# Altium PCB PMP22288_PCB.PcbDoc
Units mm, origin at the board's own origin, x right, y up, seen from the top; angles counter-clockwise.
Board outline 85.25 x 60.01 mm, 2 copper layers (Top Layer, Bottom Layer), stack 1.575 mm thick; 43 components, 22 nets, 97 pads, 29 vias.
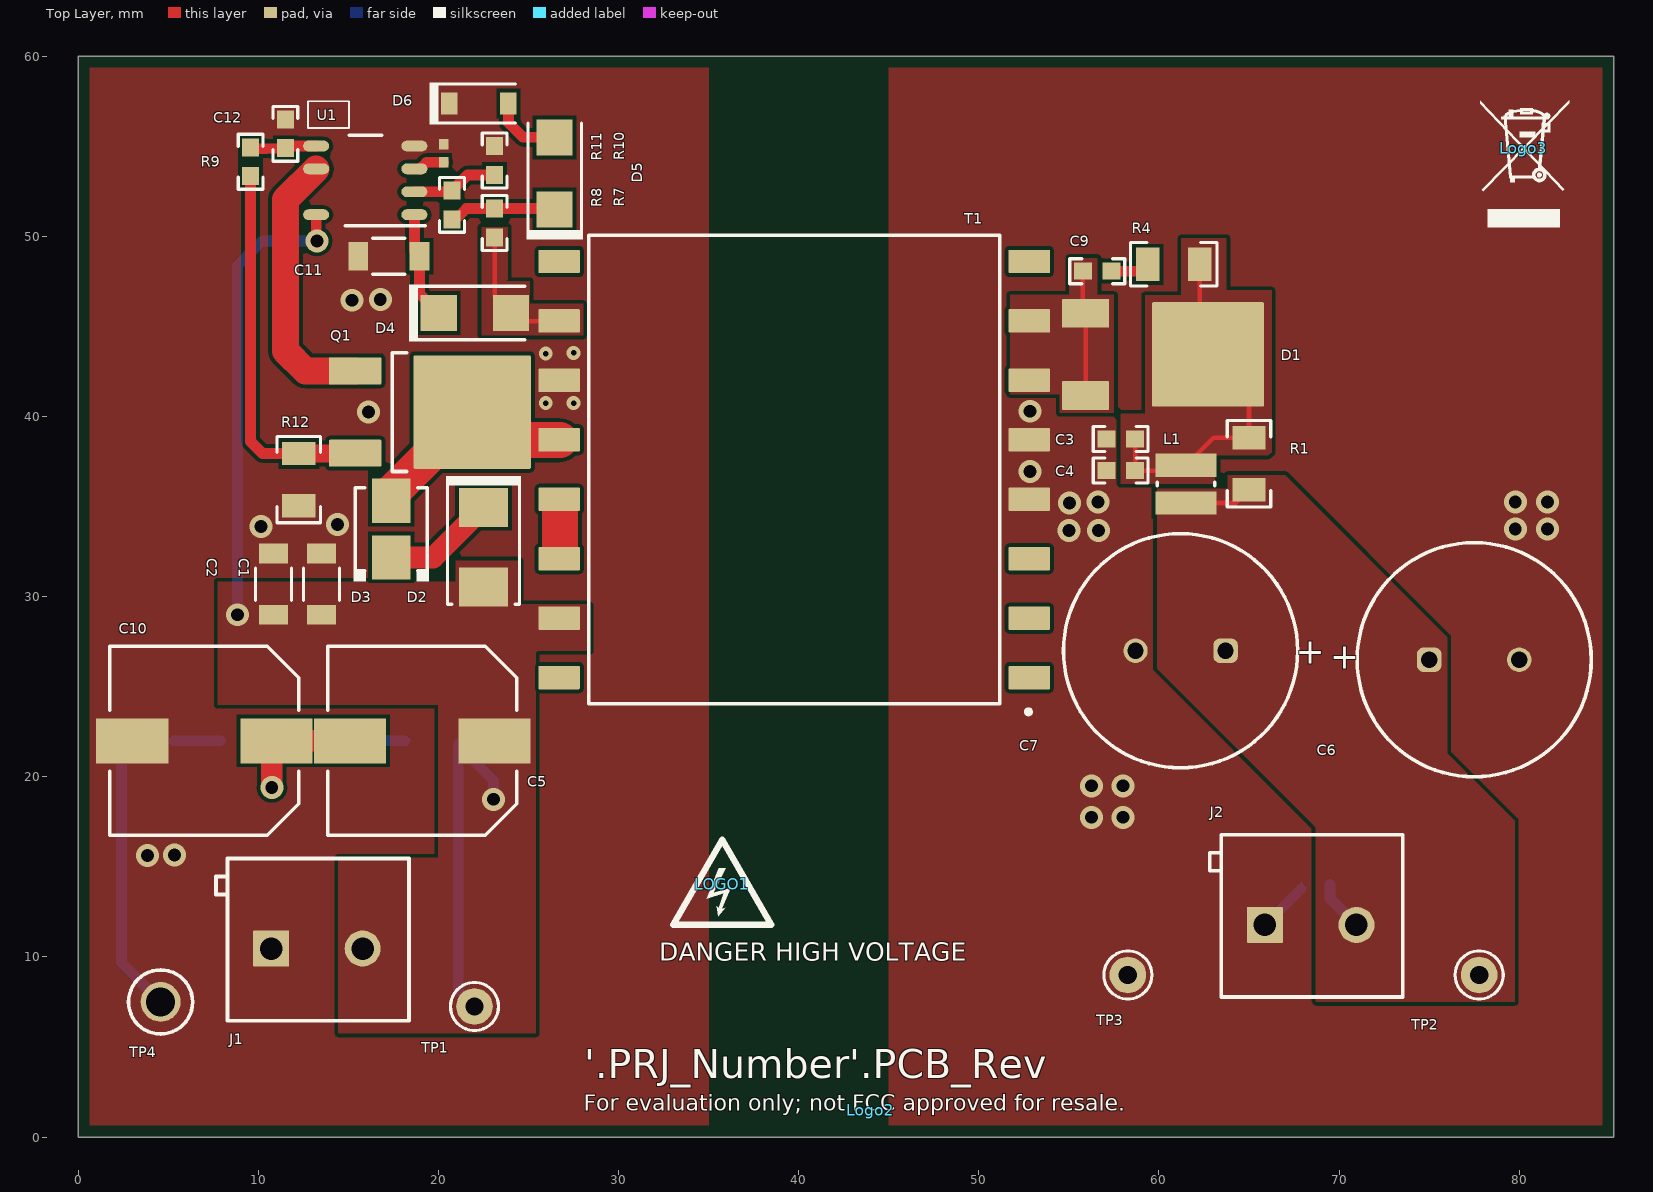
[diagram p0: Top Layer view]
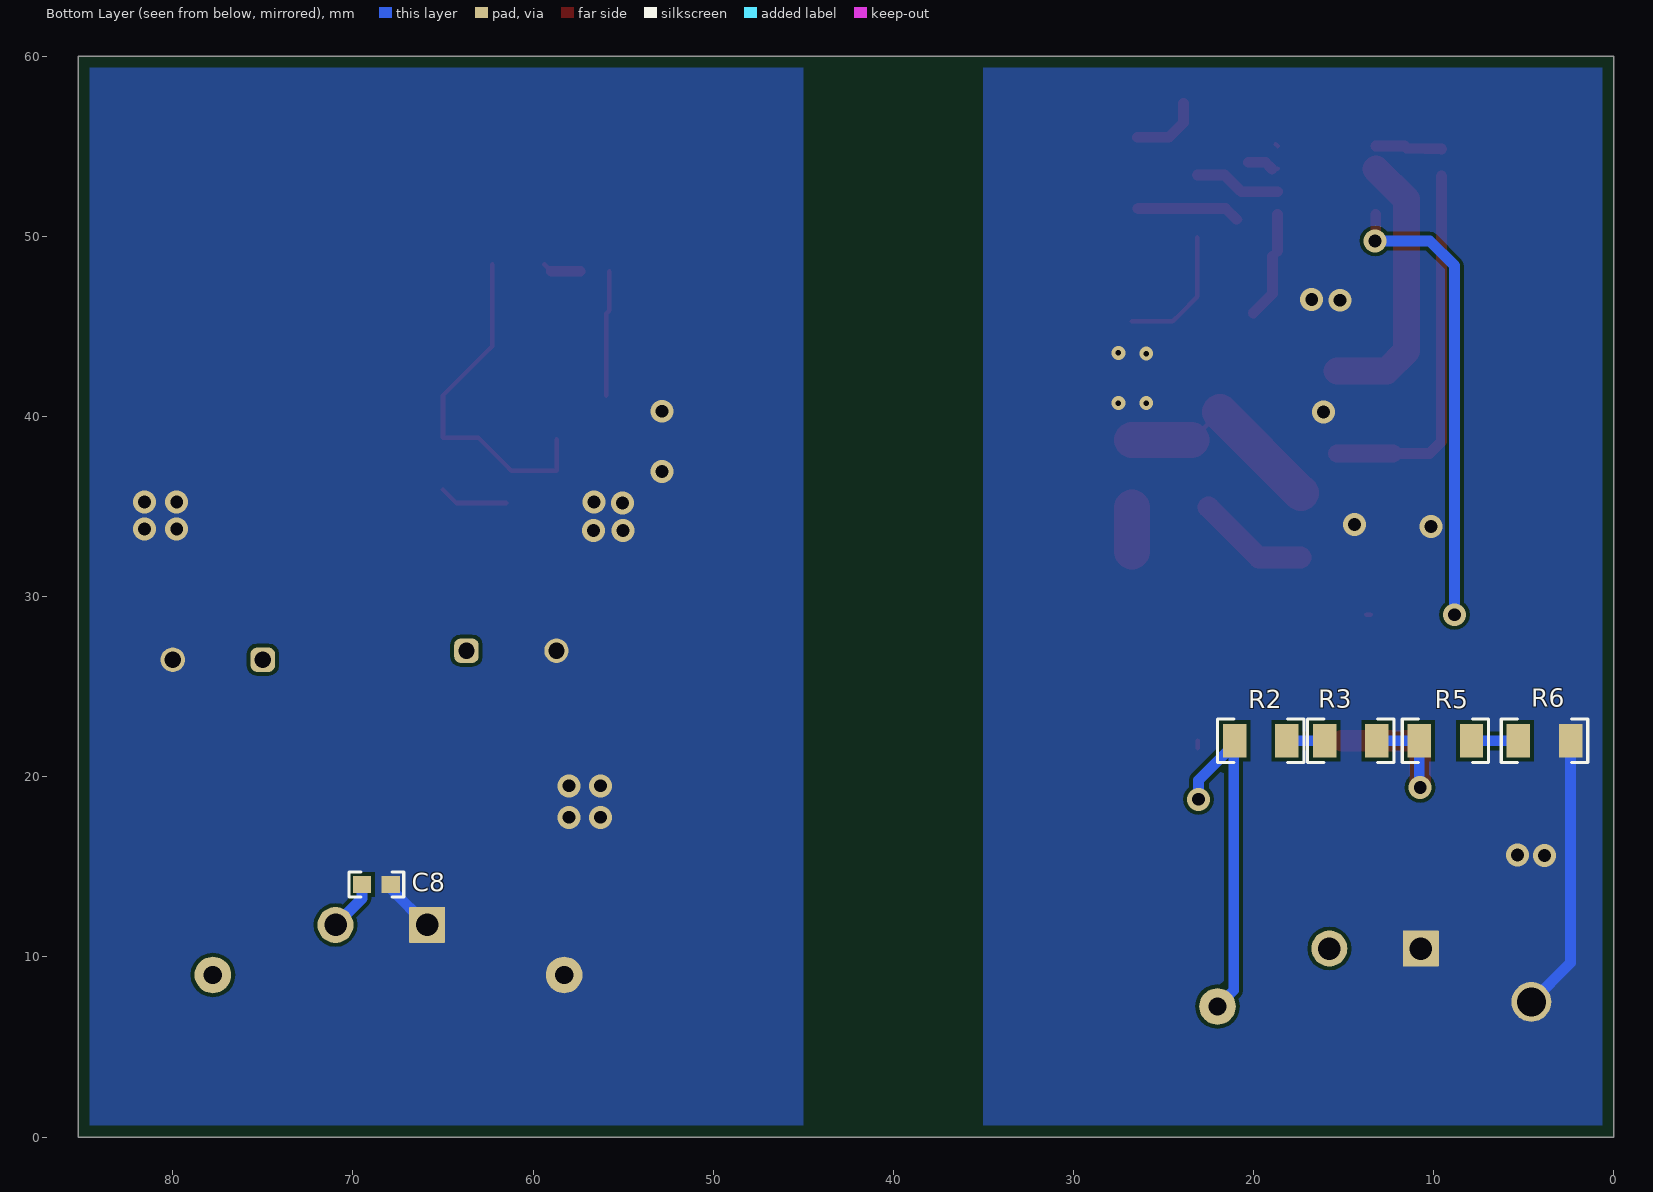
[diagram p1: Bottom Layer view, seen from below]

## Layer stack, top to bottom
Top Solder: solder mask 0.0102, Solder Resist, Dk 3.5
Top Layer: signal copper 0.0356
Dielectric1: core 1.5037, FR-4, Dk 4.8
Bottom Layer: signal copper 0.0356
Bottom Solder: solder mask 0.0102, Solder Resist, Dk 3.5

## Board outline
0,0 85.25,0 85.25,60.005 0,60.005

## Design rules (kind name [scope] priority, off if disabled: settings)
AcuteAngle [All] p1: minimum=4.50000000000000E+0001 checktracksonly=FALSE
AssemblyTestPointUsage [All] p1: valid=2
BoardOutlineClearance BoardOutlineClearance_MountingHoles [OnCopper and InComponentClass('Mounting Holes')] p1: gap=0.635 ignorepadtopadclearanceinfootprint=FALSE
BoardOutlineClearance BoardOutlineClearance_Poly [OnCopper and InPoly] p2: gap=0.635 ignorepadtopadclearanceinfootprint=FALSE
BoardOutlineClearance [OnCopper and Not InComponentClass('Logo') and not InComponentClass('FiducialMark') and not InRegion(1000,500,4000,800)] p3: gap=0.635 ignorepadtopadclearanceinfootprint=FALSE
Clearance Clearance_Keepouts [((IsTrack Or IsArc) And Not InPoly) And IsFree and IsKeepOut vs ((IsTrack Or IsArc) And Not InPoly) And IsFree and IsKeepOut] p1: gap=0 ignorepadtopadclearanceinfootprint=FALSE
Clearance Clearance_Poly [InPolygon] p2: gap=0.203 ignorepadtopadclearanceinfootprint=FALSE except(0: Arc-Hole Track-Hole SMDPad-Hole THPad-Hole Via-Hole Fill-Hole Poly-Hole Region-Hole Text-Hole)
Clearance [All] p3: gap=0.2 ignorepadtopadclearanceinfootprint=FALSE except(0: Arc-Hole Track-Hole SMDPad-Hole THPad-Hole Via-Hole Fill-Hole Poly-Hole Region-Hole Text-Hole)
ComponentClearance ComponentClearance_MountingHoles_FiducialMarks [InComponentClass('Mounting Holes') vs InComponentClass('FiducialMark')] p1: gap=1.27 collisioncheckmode=3 verticalgap=0.254 showdistances=FALSE
ComponentClearance ComponentClearance_Shunt [InComponentClass('Header') vs InComponentClass('Shunt')] p2: gap=0 collisioncheckmode=3 verticalgap=0 showdistances=FALSE
ComponentClearance ComponentClearance_Logo [InComponentClass('Logo')] p3: gap=1.27 collisioncheckmode=3 verticalgap=0.254 showdistances=FALSE
ComponentClearance ComponentClearance_ScrewToNut [(HasFootprint('NY PMS 440 0025 PH')) vs (HasFootprint('Keystone_1902C'))] p4: gap=0.127 collisioncheckmode=3 verticalgap=0.254 showdistances=FALSE
ComponentClearance ComponentClearance_MountingHoles [InComponentClass('Mounting Holes')] p5: gap=6.35 collisioncheckmode=3 verticalgap=2540 showdistances=FALSE
ComponentClearance ComponentClearance_SmallPassives [HasFootprint('0201*') or HasFootprint('0402*') or HasFootprint('0508') or HasFootprint('0603*') or HasFootprint('0612') or HasFootprint('0805*') or HasFootprint('0815*') or HasFootprint('0830*') or HasFootprint('1206*') or HasFootprint('1210*') or HasFootprint('1808*') or HasFootprint('1812*') or HasFootprint('1825*') or HasFootprint('2010*') or HasFootprint('2220*') or HasFootprint('2225*') or HasFootprint('2512*') or HasFootprint('2728*') or HasFootprint('3518*') vs HasFootprint('0201*') or HasFootprint('0402*') or HasFootprint('0508') or HasFootprint('0603*') or HasFootprint('0612') or HasFootprint('0805*') or HasFootprint('0815*') or HasFootprint('0830*') or HasFootprint('1206*') or HasFootprint('1210*') or HasFootprint('1808*') or HasFootprint('1812*') or HasFootprint('1825*') or HasFootprint('2010*') or HasFootprint('2220*') or HasFootprint('2225*') or HasFootprint('2512*') or HasFootprint('2728*') or HasFootprint('3518*')] p6: gap=0.38 collisioncheckmode=3 verticalgap=0.254 showdistances=FALSE
ComponentClearance ComponentClearance_THtoSMT [IsThruComponent vs IsSMTComponent] p7: gap=0.381 collisioncheckmode=3 verticalgap=0.762 showdistances=FALSE
ComponentClearance ComponentClearance_THtoTH [IsThruComponent vs IsThruComponent] p8: gap=0.381 collisioncheckmode=3 verticalgap=0.762 showdistances=FALSE
ComponentClearance [All] p9: gap=0.381 collisioncheckmode=3 verticalgap=0.254 showdistances=FALSE
DiffPairsRouting [All] p1: maxlimit=2.54 minlimit=0.254 mostfreqgap=0.254 toplayer_minwidth=0.381 toplayer_maxwidth=0.381 toplayer_prefwidth=0.381 bottomlayer_minwidth=0.381 bottomlayer_maxwidth=0.381 bottomlayer_prefwidth=0.381 maxuncoupledlength=25.4
FabricationTestPointUsage TestPointUsage [All] p1: valid=2 allowmultiple=FALSE
FabricationTestpoint Testpoint [All] p1: side=3 testpointundercomponent=TRUE minsize=1.016 maxsize=2.54 preferedsize=1.524 minholesize=0 maxholesize=1.016 preferedholesize=0.813 testpointgrid=0.025 allowsidetop=TRUE allowsidebottom=TRUE usegrid=TRUE gridtolerance=0
FanoutControl Fanout_LCC [IsLCC] p1: bgadir=Out bgaviamode=Centered fanoutstyle=Auto fanoutdirection=Alternating viagrid=0.025 // Fanout_LCC (Default Rule)
FanoutControl Fanout_BGA [IsBGA] p2: bgadir=Out bgaviamode=Centered fanoutstyle=Auto fanoutdirection=Alternating viagrid=0.025 // Fanout_BGA (Default Rule)
FanoutControl Fanout_Default [All] p4: bgadir=Out bgaviamode=Centered fanoutstyle=Auto fanoutdirection=Alternating viagrid=0.025 // Fanout_Default (Default Rule)
FanoutControl Fanout_Small [(CompPinCount < 5)] p5: bgadir=Out bgaviamode=Centered fanoutstyle=Auto fanoutdirection=OutThenIn viagrid=0.025 // Fanout_Small (Default Rule)
HoleSize [All] p1: absolutevalues=TRUE maxlimit=6.375 minlimit=0.2 maxpercent=80.000 minpercent=20.000
MinimumAnnularRing MinimumAnnularRing_ThermalPadVias [IsVia and InAnyComponent] p1: minimumring=0.15
MinimumAnnularRing [All] p2: minimumring=0.203
MinimumSolderMaskSliver MinimumSolderMaskSliver_Logo [InComponentClass('Logo') vs InComponentClass('Logo')] p1: minsoldermaskwidth=0.018
MinimumSolderMaskSliver [All] p2: minsoldermaskwidth=0.1
PlaneConnect [All] p1: planeconnectstyle=Direct reliefexpansion=0.254 reliefentries=4 reliefconductorwidth=0.254 reliefairgap=0.254
PolygonConnect [All] p1: connectstyle=Direct reliefconductorwidth=0.254 reliefentries=4 polygonreliefangle="90 Angle" airgapwidth=0.254
RoutingVias ThermalPadVias [IsVia and InAnyComponent] p1: holewidth=0.2 width=0.5 viastyle="Through Hole" minholewidth=0.2 minwidth=0.5 maxholewidth=0.33 maxwidth=0.6
RoutingVias [All] p2: holewidth=0.406 width=0.864 viastyle="Through Hole" minholewidth=0.2 minwidth=0.66 maxholewidth=1.016 maxwidth=1.651
SilkToBoardRegionClearance [Not ((IsComment or IsDesignator) And (Hide <> 'False')) and not InRegion(1000,500,4000,800)] p1:
SilkToSilkClearance SilkToSilkClearance_Pb-FreeLogo [(HasFootprint('Pb-Free_Overlay_Medium') OR HasFootprint('Pb-Free_Overlay_Small')) vs (HasFootprint('Pb-Free_Overlay_Medium') OR HasFootprint('Pb-Free_Overlay_Small'))] p1: silktosilkclearance=0
SilkToSilkClearance [All] p2: silktosilkclearance=0.102
SilkToSolderMaskClearance SilkToComponentPadClearance [IsPad and InAnycomponent] p1: minsilkscreentomaskgap=0.127 clearancetoexposedcopper=TRUE
SilkToSolderMaskClearance "Silk to Solder Mask Opening" [All] p2: minsilkscreentomaskgap=0.102 clearancetoexposedcopper=FALSE
SolderMaskExpansion [All] p1: expansion=0.05
Width [All] p1: maxlimit=2.54 minlimit=0.152 preferedwidth=0.254 checkconnectedcopper=TRUE
15 further rules are at their usual default settings.

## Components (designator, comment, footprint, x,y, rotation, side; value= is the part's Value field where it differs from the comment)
C1 "C1206C223KDRACTU" 1206_190 13.5,30.7 r90 top value=0.022uF
C2 "C1206C223KDRACTU" 1206_190 10.85,30.7 r90 top value=0.022uF
C3 "GRM188R71E105KA12D" 0603 57.873,38.75 r180 top value=1uF
C4 "GRM188R71E105KA12D" 0603 57.873,37 r180 top value=1uF
C5 "ULV2G100MNL1GS" ULV_1000x1350 19.1,22 r180 top value=10uF
C6 "EEU-FC1V391S" FC_1250x1500 77.5,26.5 r0 top value=390uF
C7 "EEU-FC1V391S" FC_1250x1500 61.198,27 r180 top value=390uF
C8 "C0603C104K5RACAUTO" 0603 68.698,14.025 r180 bottom value=0.1uF
C9 "CGA3E2X7R2A103K080AA" 0603 56.575,48.069 r180 top value=0.01uF
C10 "ULV2G100MNL1GS" ULV_1000x1350 7,22 r180 top value=10uF
C11 "CGA5L1X7R1V106K160AC" 1206_190 17.25,48.899 r180 top value=10uF
C12 "CGA3E2NP01H101J080AA" 0603 11.5,55.695 r90 top value=100pF
D1 "MBRD20200CT-13" DPAK 59.323,43.45 r0 top value=200V
D2 "1SMB5956BT3G" SMB 22.5,32.75 r270 top value=200V
D3 "EGF1T-E3/67A" DO-214BA 17.375,33.75 r90 top value=1300V
D4 "US1J-E3/5AT" SMA 22.017,45.75 r0 top value=600V
D5 "US1J-E3/5AT" SMA 26.451,53.499 r90 top value=600V
D6 "DDZ20CQ-7" SOD-123 22.25,57.382 r0 top value=20V
J1 "ED120/2DS" On-Shore_ED120_2DS 13.25,10.466 r0 top
J2 "ED120/2DS" On-Shore_ED120_2DS 68.423,11.775 r0 top
L1 "784383350047" WE-MAIA_3015 61.498,36.25 r270 top value=470nH
LOGO1 "DANGER HIGH VOLTAGE" IEC_HighVoltage_Small 35.75,14.025 r0 top
Logo2 "FCC disclaimer" FCC_disclaimer 44,1.5 r0 top
Logo3 "WEEE logo" WEEE_Minimum 80.25,54.895 r0 top
Q1 "STD3N95K5AG" FP-STD3N95K5AG_DPAK-MFG 19.525,40.249 r270 top
R1 "CRCW12060000Z0EA" 1206 64.998,37.381 r270 top value=0
R2 "CRCW12061M00FKEA" 1206 19.6,22 r180 bottom value=1.00Meg
R3 "CRCW12061M00FKEA" 1206 14.6,22 r180 bottom value=1.00Meg
R4 "CRCW12060000Z0EA" 1206 60.823,48.45 r0 top value=0
R5 "CRCW12061M00FKEA" 1206 9.35,22 r180 bottom value=1.00Meg
R6 "CRCW12061M00FKEA" 1206 3.85,22 r180 bottom value=1.00Meg
R7 "CRCW060323K2FKEA" 0603 23.119,50.741 r270 top value=23.2k
R8 "CRCW06031K69FKEA" 0603 20.75,51.75 r270 top value=1.69k
R9 "CRCW06031K02FKEA" 0603 9.572,54.145 r270 top value=1.02k
R10 "CRCW06038K66FKEA" 0603 23.119,54.216 r270 top value=8.66k
R11 "CRCW0402332KFKED" 0402L 20.294,54.616 r270 top value=332k
R12 "CSR1206FT1R00" 1206 12.25,36.5 r90 top value=1.00
T1 "P302264-A1-51" FP-P302264-A1-51_SMD_TRANSFORMER_26MM0_22MM8-MFG 39.75,37.058 r90 top
TP1 "5000" Keystone5000 22,7.25 r90 top
TP2 "5000" Keystone5000 77.773,9 r270 top
TP3 "5001" Keystone5001 58.273,9 r270 top
TP4 "5011" Keystone5011 4.575,7.5 r0 top
U1 "UCC28730QDRQ1" D0007A_N 15.937,53.114 r180 top

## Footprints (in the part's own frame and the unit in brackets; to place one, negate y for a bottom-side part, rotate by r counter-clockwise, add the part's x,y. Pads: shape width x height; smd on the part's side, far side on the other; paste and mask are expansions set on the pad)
0402L [mm] "0402 from SM-752 data"
  rect 0.6x0.5 smd: 1(-0.5,0) 2(0.5,0)
  body extent -0.55,-0.3 0.55,0.3, height 0.6
0603 [mm] "0603 from SM-752 data"
  rect 1x0.95 smd: 1(-0.8,0) 2(0.8,0)
  silkscreen extent -1.52,-0.69 1.52,0.69, body extent -0.87,-0.47 0.87,0.47, height 1
1206 [mm] "1206 from SM-752 data"
  rect 1.3x1.85 smd: 1(-1.45,0) 2(1.45,0)
  silkscreen extent -2.4,-1.21 2.4,1.21, body extent -1.7,-0.9 1.7,0.9, height 1.35
1206_190 [mm] "1206_190"
  rect 1.1x1.6 smd: 1(-1.7,0) 2(1.7,0)
  silkscreen extent -0.9,-1 0.9,1, body extent -1.75,-0.95 1.75,0.95, height 1.9
D0007A_N [mm] "SOIC, 7-Leads, Body 4.9x3.9mm, Pitch 1.27mm, IPC Medium Density"
  oval 1.45x0.6 smd: 1(-2.725,1.905) 2(-2.725,0.635) 3(-2.725,-0.635) 4(-2.725,-1.905) 5(2.725,-1.905) 6(2.725,-0.635) 8(2.725,1.905)
  silkscreen extent -3.32,-2.5 1.1,2.52, body extent -3.01,-2.45 3.01,2.45, height 1.75
DO-214BA [mm] "Molded Diode, 2-Leads, Body 4.3x3.6mm, IPC Medium Density"
  rect 2.45x2.15 smd: 1(-1.575,0) 2(1.575,0)
  silkscreen extent -2.92,-2.1 2.3,2.1, body extent -2.29,-1.97 2.28,1.97, height 3.3
DPAK [mm] "D-PAK, 3-Pads, Body 6.22x6.73mm (max), TO-252AA using nominal STEP model"
  rrect6% 2.6x1.6 smd: 1(-3.4,2.28) 3(-3.4,-2.28)
  rrect2% 6.2x5.8 smd paste-3: 2(3.4,0)
  body extent -3.86,-3.29 5.84,3.29, height 2.48
FC_1250x1500 [mm] "TH, 2-Leads, Dia 12.5mm, Pin Spacing 5mm"
  rrect50% 1.35x1.35 hole 0.9: 1(-2.5,0)
  round 1.35 hole 0.9: 2(2.5,0)
  silkscreen extent -6.5,-6.5 6.5,6.5, body extent -6.5,-6.5 6.51,6.5, height 16.01
FCC_disclaimer [mm]
FP-P302264-A1-51_SMD_TRANSFORMER_26MM0_22MM8-MFG [mm]
  rrect8% 1.3x2.3 smd paste+0 mask+0: 1(-11.55,-13.05) 2(-8.25,-13.05) 3(-4.95,-13.05) 4(-1.65,-13.05) 5(1.65,-13.05) 6(4.95,-13.05) 7(8.25,-13.05) 8(11.55,-13.05) 9(11.55,13.05) 10(8.25,13.05) 11(4.95,13.05) 12(1.65,13.05) 13(-1.65,13.05) 14(-4.95,13.05) 15(-8.25,13.05) 16(-11.55,13.05)
  silkscreen extent -13.57,-13.13 13,11.4, body extent -13.1,-14.3 13.1,14.3, height 0.25
FP-STD3N95K5AG_DPAK-MFG [mm]
  rrect7% 1.5x2.9 smd paste+0 mask+0: 1(-2.286,-4.15) 3(2.286,-4.15)
  rrect2% 6.3x6.5 smd paste+0 mask+0: 4(0,2.35)
  silkscreen extent -3.3,-2.09 3.3,-1.28, body extent -3.4,-5.7 3.4,5.7, height 0.25
IEC_HighVoltage_Small [mm]
  silkscreen extent -2.72,-2.24 2.72,2.47
Keystone5000 [mil] "For Keystone 500x miniature loop terminals"
  round 80 hole 40: 1(0,0)
  silkscreen extent -52,-52 52,52, body extent -49,-49 49,49, height 182
Keystone5001 [mil] "For Keystone 500x miniature loop terminals"
  round 80 hole 40: 1(0,0)
  silkscreen extent -52,-52 52,52, body extent -49,-49 49,49, height 182
Keystone5011 [mil] "Keystone Multipurpose loops"
  round 87 hole 63: 1(0,0)
  silkscreen extent -70,-70 70,70, body extent -63,-63 63,62, height 319
On-Shore_ED120_2DS [mm] "ONSHORE"
  rrect5% 2x2 hole 1.25: 1(-2.54,0)
  round 2 hole 1.25: 2(2.54,0)
  silkscreen extent -5.6,-4 5.12,5, body extent -5.78,-4 5.08,5, height 13
SMA [mm] "Molded Diode, 2-Leads, Body 4.3x2.6mm, IPC Medium Density, based on OnSemi component dimensions and land pattern"
  rect 2x2 smd: 1(-2,0) 2(2,0)
  silkscreen extent -3.66,-1.57 2.79,1.57, body extent -2.6,-1.3 2.6,1.3, height 2.42
SMB [mm] "Molded Diode, 2-Leads, Body 5.4x3.6mm, IPC Medium Density, based on OnSemi component dimensions"
  rect 2.159x2.743 smd: 1(-2.21,0) 2(2.21,0)
  silkscreen extent -3.94,-2.08 3.18,2.08, body extent -2.7,-1.8 2.7,1.8, height 2.32
SOD-123 [mm] "On Semi recommended land pattern"
  rect 0.915x1.22 smd: 1(-1.637,0) 2(1.637,0)
  silkscreen extent -2.74,-1.17 2.03,1.17, body extent -1.93,-0.9 1.93,0.9, height 1.35
ULV_1000x1350 [mm] "SMD, 2-Leads, Dia 10mm"
  rect 4x2.5 smd: 1(-4,0) 2(4,0)
  silkscreen extent -5.25,-5.25 5.25,5.25, body extent -5.25,-5.25 5.25,5.25, height 14.51
WE-MAIA_3015 [mm] "SMD, 2-Leads, Body 3x3mm"
  rect 1.3x3.4 smd: 1(-1.05,0) 2(1.05,0)
  silkscreen extent -0.1,-1.6 0.1,1.6, body extent -1.6,-1.6 1.6,1.6, height 1.5
WEEE_Minimum [mm] "WEEElie bin"
  silkscreen extent -2.42,-4.38 2.52,2.65

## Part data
C1 C2: library part CMP-0084048-1, "CAP, CERM, 0.022 µF, 1000 V,+/- 10%, X7R, AEC-Q200 Grade 1, 1206", Cap_Case=1206, Manufacturer=Kemet, TempCo=X7R, Tolerance_%=10%, Value2=1000V, ValueDisplayed=0.022µF
C3 C4: library part CMP-0007405-4, "CAP, CERM, 1 uF, 25 V, +/- 10%, X7R, 0603", Cap_Case=0603, Manufacturer=MuRata, Supplier Part Number 1=490-5307-1-ND, TempCo=X7R, Tolerance_%=10%, Value1=Unknown, Value2=25V, ValueDisplayed=1uF
C5 C10: library part CMP-0011436-2, "CAP, AL, 10 uF, 400 V, +/- 20%, SMD", Cap_Case=10x13.5mm, Manufacturer=Nichicon, Supplier Part Number 1=493-6741-1-ND, Tolerance_%=20%, Value1=Unknown, Value2=400V, ValueDisplayed=10uF
C6 C7: library part CMP-0860943-1, "CAP, AL, 390 µF, 35 V, +/- 20%, AEC-Q200 Grade 2, TH", Cap_Case=12.5x15mm, Manufacturer=Panasonic, Tolerance_%=20%, Value2=35V, ValueDisplayed=390µF
C8: library part CMP-0079602-1, "CAP, CERM, 0.1 µF, 50 V,+/- 10%, X7R, AEC-Q200 Grade 1, 0603", Cap_Case=0603, Manufacturer=Kemet, Supplier Part Number 1=399-6856-1-ND, TempCo=X7R, Tolerance_%=10%, Value2=50V, ValueDisplayed=0.1µF
C9: library part CMP-0007082-1, "CAP, CERM, 0.01 uF, 100 V, +/- 10%, X7R, AEC-Q200 Grade 1, 0603", Cap_Case=0603, Manufacturer=TDK, Supplier Part Number 1=445-5812-1-ND, TempCo=X7R, Tolerance_%=10%, Value1="0.235428 ohm", Value2=100V, ValueDisplayed=0.01uF
C11: library part CMP-0008772-2, "CAP, CERM, 10 uF, 35 V, +/- 10%, X7R, AEC-Q200 Grade 1, 1206_190", Cap_Case=1206_190, Manufacturer=TDK, Supplier Part Number 1=445-174428-1-ND, TempCo=X7R, Tolerance_%=10%, Value1="0.002229 ohm", Value2=35V, ValueDisplayed=10uF
C12: library part CMP-0007075-4, "CAP, CERM, 100 pF, 50 V, +/- 5%, C0G/NP0, AEC-Q200 Grade 0, 0603", Cap_Case=0603, Manufacturer=TDK, Supplier Part Number 1=445-12386-1-ND, TempCo=C0G/NP0, Tolerance_%=5%, Value1=Unknown, Value2=50V, ValueDisplayed=100pF
D1: library part CMP-0081704-3, "Diode, Schottky, 200 V, 10 A, AEC-Q101, DPAK", Manufacturer="Diodes Inc.", Value1=10A, Value2=0.9V
D2: library part CMP-0005624-4, "Diode, Zener, 200 V, 550 mW, SMB", Manufacturer="ON Semiconductor", Power_W=550mW, Value1=0.55W
D3: library part CMP-0077733-2, "Diode, Ultrafast, 1300 V, 1 A, AEC-Q101, DO-214BA", Manufacturer=Vishay-Semiconductor, Value1=1A, Value2=3V
D4 D5: library part CMP-0029149-2, "Diode, Ultrafast, 600 V, 1 A, AEC-Q101, SMA", Manufacturer=Vishay-Semiconductor, Value1=1A, Value2=1.7V
D6: library part CMP-0085147-1, "Diode, Zener, 20 V, 500 mW, AEC-Q101, SOD-123", Manufacturer="Diodes Inc.", Power_W=500mW, Value1=0.5W
J1 J2: library part CMP-0074910-1, "Terminal Block, 5.08 mm, 2x1, Brass, TH", Color=Blue, Current_A=15A, Manufacturer="On-Shore Technology", Supplier Part Number 1=ED1609-ND, Voltage_V=300V
L1: library part CMP-0064355-1, "Inductor, Shielded, Powdered Iron, 470 nH, 4.6 A, 0.023 ohm, AEC-Q200 Grade 1, SMD", Manufacturer="Wurth Elektronik", Supplier Part Number 1=732-6935-1-ND, Value1="0.023 ohm", Value2=4.6A, ValueDisplayed=470nH
LOGO1: library part CMP-0074835-1, "IEC 61010-1 High Voltage Warning"
Logo2: library part CMP-0074847-1, "FCC_disclaimer"
Logo3: library part CMP-0074769-1
Q1: library part CMP-0088095-1, "N-Channel 950V 2A (Tc) 45W (Tc) Surface Mount DPAK", Manufacturer=STMicroelectronics
R1 R4: library part CMP-0018573-3, "RES, 0, 5%, 0.25 W, AEC-Q200 Grade 0, 1206", Manufacturer=Vishay-Dale, Power_W=250mW, Supplier Part Number 1=541-0.0ECT-ND, TempCo="200 ppm/C", Tolerance_%=5%, Value2=0.25W, Value_Code=0000, ValueDisplayed=0
R2 R3 R5 R6: library part CMP-0016716-3, "RES, 1.00 M, 1%, 0.25 W, AEC-Q200 Grade 0, 1206", Manufacturer=Vishay-Dale, Power_W=250mW, Supplier Part Number 1=541-1.00MFCT-ND, TempCo="100 ppm/C", Tolerance_%=1%, Value2=0.25W, Value_Code=1M00, ValueDisplayed=1.00M
R7: library part CMP-0022228-4, "RES, 23.2 k, 1%, 0.1 W, AEC-Q200 Grade 0, 0603", Manufacturer=Vishay-Dale, Power_W=100mW, Supplier Part Number 1=541-23.2KHCT-ND, TempCo="100 ppm/C", Tolerance_%=1%, Value2=0.1W, Value_Code=23k2, ValueDisplayed=23.2k
R8: library part CMP-0022131-4, "RES, 1.69 k, 1%, 0.1 W, AEC-Q200 Grade 0, 0603", Manufacturer=Vishay-Dale, Power_W=100mW, Supplier Part Number 1=541-1.69KHCT-ND, TempCo="100 ppm/C", Tolerance_%=1%, Value2=0.1W, Value_Code=1k69, ValueDisplayed=1.69k
R9: library part CMP-0022110-4, "RES, 1.02 k, 1%, 0.1 W, AEC-Q200 Grade 0, 0603", Manufacturer=Vishay-Dale, Power_W=100mW, Supplier Part Number 1=541-1.02KHCT-ND, TempCo="100 ppm/C", Tolerance_%=1%, Value2=0.1W, Value_Code=1k02, ValueDisplayed=1.02k
R10: library part CMP-0022637-4, "RES, 8.66 k, 1%, 0.1 W, AEC-Q200 Grade 0, 0603", Manufacturer=Vishay-Dale, Power_W=100mW, Supplier Part Number 1=541-8.66KHCT-ND, TempCo="100 ppm/C", Tolerance_%=1%, Value2=0.1W, Value_Code=8k66, ValueDisplayed=8.66k
R11: library part CMP-0026296-2, "RES, 332 k, 1%, 0.063 W, AEC-Q200 Grade 0, 0402", Manufacturer=Vishay-Dale, Power_W=63mW, Supplier Part Number 1=541-332KLCT-ND, TempCo="100 ppm/C", Tolerance_%=1%, Value2=0.063W, Value_Code=332k
R12: library part CMP-0017272-2, "RES, 1.00, 1%, 0.5 W, 1206", Manufacturer="Stackpole Electronics Inc", Power_W=500mW, Supplier Part Number 1=CSR1206FT1R00CT-ND, TempCo="100 ppm/C", Tolerance_%=1%, Value2=0.5W, Value_Code=1R00, ValueDisplayed=1.00
T1: library part CMP-0088107-1, "Flyback Transformer", Manufacturer=TDK
TP1 TP2: library part CMP-0055137-1, "Test Point, Miniature, Red, TH", Color=Red, Manufacturer=Keystone, Supplier Part Number 1=36-5000-ND
TP3: library part CMP-0055138-1, "Test Point, Miniature, Black, TH", Color=Black, Manufacturer=Keystone, Supplier Part Number 1=36-5001-ND
TP4: library part CMP-0055148-1, "Test Point, Multipurpose, Black, TH", Color=Black, Manufacturer=Keystone, Supplier Part Number 1=36-5011-ND
U1: library part CMP-0065056-3, "Zero Standby PSR Flyback Controller with CVCC and Wake-Up Monitoring, Automotive, D0007A (SOIC-7)", Alternate Manufacturer="Texas Instruments"

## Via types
v1: diameter 1.27, hole 0.711, Top Layer to Bottom Layer, 25 vias
v2: diameter 0.762, hole 0.305, Top Layer to Bottom Layer, 4 vias

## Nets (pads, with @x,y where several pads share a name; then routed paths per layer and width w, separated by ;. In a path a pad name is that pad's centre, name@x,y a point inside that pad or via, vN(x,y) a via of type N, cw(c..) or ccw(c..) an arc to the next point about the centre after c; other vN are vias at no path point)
Aux: D4.2 R7.2 T1.10 | length 7.5
  Top Layer w0.254: R7.2 23.119,46.648 D4.2 24.478,45.289 T1.10@26.747,45.289
CBC: R11.2 U1.3 | length 1.8
  Top Layer w0.254: U1.3 U1.3@18.978,53.749
  Top Layer w0.6: U1.3@18.978,53.749 19.345,54.116 R11.2
CS: C12.1 R9.1 U1.5 | length 3.7
  Top Layer w0.254: C12.1 C12.1@11.623,55.019
  Top Layer w0.6: R9.1@9.572,54.858 C12.1 ; C12.1@11.623,55.019 U1.5
DRV: Q1.1 U1.6 | length 15.1
  Top Layer w1.5: U1.6 11.5,52.036 11.5,43.65 12.615,42.535 Q1.1
GND: C3.2 C4.2 C6.2 C7.2 C8.2 J2.1 T1.4 T1.5 TP3.1 | length 3.1
  Bottom Layer w0.254: C8.2@67.898,13.79 C8.2
  Bottom Layer w0.6: J2.1 C8.2@67.898,13.79
  other v1: 56.25,17.75 58,17.75 56.25,19.5 58,19.5 55,33.677 56.641,33.677 79.783,33.75 81.569,33.75 55.025,35.2 56.608,35.25 79.783,35.25 81.569,35.25 52.847,36.957 52.847,40.293
HV: C1.1 C2.1 C5.1 D2.2 J1.2 R2.1 T1.15 TP1.1 U1.8 | length 45.4
  Top Layer w0.254: v1@13.213,50.234 13.25,50.197 v1(13.25,49.749) ; C1.1 C1.1@13.75,29 ; C5.1@23.1,21.6 C5.1
  Top Layer w0.6: v1@13.213,50.234 U1.8
  Bottom Layer w0.254: R2.1 21.05,21.815 R2.1@21.1,21.765
  Bottom Layer w0.6: v1(8.85,29) 8.85,48.38 10.219,49.749 v1(13.25,49.749) ; TP1.1 21.1,8.15 21.1,21.765 23.055,19.81 v1(23.055,18.75)
NetC3_1: C3.1 C4.1 D1.2 L1.1 R1.1 R4.2 | length 19.6
  Top Layer w0.254: C3.1 C4.1 61.198,37 L1.1 63.029,38.831 R1.1 64.998,41.175 D1.2 62.273,43.9 R4.2
NetC5_2: C5.2 C10.1 R3.2 R5.1 | length 11.8
  Top Layer w1.2: v1(10.75,19.405) 10.75,21.75 C10.1 C5.2
  Bottom Layer w0.6: v1(10.75,19.405) 10.8,19.455 R5.1 R3.2
NetC9_1: C9.1 R4.1 | length 2.2
  Top Layer w0.254: R4.1@58.992,48.069 R4.1
  Top Layer w0.6: C9.1 R4.1@58.992,48.069
NetC9_2: C9.2 D1.1 D1.3 T1.6 T1.7 | length 7
  Top Layer w0.254: C9.2 55.775,45.878 D1.1 D1.3
NetD2_1: D2.1 D3.1 | length 6.3
  Top Layer w1.2: D3.1 19.715,32.175 D2.1
NetD3_2: D3.2 Q1.4 T1.12 | length 12.3
  Top Layer w0.254: D3.2 D3.2@17.375,35.749 ; Q1.4 Q1.4@23.435,38.689
  Top Layer w2: D3.2@17.375,35.749 Q1.4 ; Q1.4@23.435,38.689 T1.12@26.747,38.689
NetD5_1: D5.1 R7.1 R8.2 | length 6
  Top Layer w0.254: R8.2 R8.2@20.949,50.95 ; D5.1@26.408,51.541 D5.1
  Top Layer w0.6: R8.2@20.949,50.95 21.541,51.541 R7.1 D5.1@26.408,51.541
NetD5_2: D5.2 D6.2 | length 4
  Top Layer w0.6: D6.2 23.888,56.313 24.701,55.5 D5.2@26.45,55.5
NetQ1_3: Q1.3 R9.2 R12.2 | length 20.8
  Top Layer w0.254: Q1.3@15.362,37.95 Q1.3
  Top Layer w0.6: R9.2 9.572,38.616 10.238,37.95 R12.2
  Top Layer w1: R12.2 Q1.3@15.362,37.95
NetR2_2: R2.2 R3.1 | length 2.1
  Bottom Layer w0.6: R3.1 R2.2
NetR5_2: R5.2 R6.1 | length 2.6
  Bottom Layer w0.6: R6.1 R5.2
NetT1_13: T1.13 T1.14 | length 2.5
  Top Layer w2: T1.14@26.747,32.5 T1.13@26.747,34.96
PGND: C1.2 C2.2 C10.2 C11.2 C12.2 D6.1 J1.1 R6.2 R10.1 R11.1 R12.1 T1.11 TP4.1 U1.4 | length 15.5
  Top Layer w0.254: U1.4 U1.4@18.759,55.116
  Bottom Layer w0.6: R6.2 2.4,9.675 TP4.1
  other v1: 3.85,15.64 5.35,15.665 10.152,33.897 14.392,34 16.125,40.25 15.197,46.457 16.772,46.5
  other v2: 25.951,40.75 27.5,40.75 25.951,43.496 27.5,43.528
VDD: C11.1 D4.1 U1.1 | length 6
  Top Layer w0.254: C11.1@18.663,49.187 C11.1
  Top Layer w0.6: C11.1@18.663,49.187 U1.1 ; C11.1 18.95,46.817 D4.1
Vout: C6.1 C7.1 C8.1 J2.2 L1.2 R1.2 TP2.1 | length 6.7
  Top Layer w0.254: L1.2 64.267,35.2 R1.2
  Bottom Layer w0.6: C8.1 69.498,13.24 J2.2
VS: R8.1 R10.2 U1.2 | length 4.8
  Top Layer w0.254: R8.1@20.679,52.479 R8.1
  Top Layer w0.6: U1.2 R8.1@20.679,52.479 ; R8.1 21.616,53.416 R10.2
pads on no net: T1.1 T1.2 T1.3 T1.8 T1.9 T1.16

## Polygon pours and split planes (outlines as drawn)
GND on Top Layer "TOP_LAYER_GND_P043" (solid, remove dead copper, pour order 43): 45,60.005 45,0 85.25,0 85.25,60.005
PGND on Top Layer "TOP_LAYER_PGND_P041" (solid, remove dead copper, pour order 41): 0,60.005 0,0 35,0 35,60.005
Vout on Top Layer "TOP_LAYER_VOUT_P039" (solid, remove dead copper, pour order 39): 67,36.75 63.823,36.75 63.823,36 59.898,36 59.898,26 68.698,17.2 68.698,7.552 68.75,7.5 79.75,7.5 79.75,17.554 76,21.304 76,27.75
no net on Top Layer "TOP_LAYER_NONET_P037" (solid, remove dead copper, pour order 37): 59.623,36
NetC9_2 on Top Layer "TOP_LAYER_NETC9_2_P035" (solid, remove dead copper, pour order 35): 55.025,46.75 51.75,46.75 51.75,41.25 54.5,41.25 54.5,40.221 57.5,40.221 57.5,46.75 56.575,46.75 56.575,48.794 55.025,48.794
no net on Top Layer "TOP_LAYER_NONET_P033" (solid, remove dead copper, pour order 33): 18.25,43.549
Aux on Top Layer "TOP_LAYER_AUX_P029" (solid, remove dead copper, pour order 29): 22.394,50.5 22.394,44.5 28.025,44.5 28.025,46.25 25.067,46.25 25.067,47.5 23.75,47.5 23.844,47.594 23.844,50.5
NetC3_1 on Top Layer "TOP_LAYER_NETC3_1_P027" (solid, remove dead copper, pour order 27): 57.895,40.15 57.873,40.129 57.873,36.275 63.073,36.275 63.098,36.25 63.098,37.85 66.073,37.85 66.173,37.75 66.248,37.825 66.248,47 63.749,47 63.748,46.999 63.748,49.895 61.276,49.895 61.248,49.923 61.248,46.73 59.248,46.73 59.248,40.15
no net on Top Layer "TOP_LAYER_NONET_P021" (solid, remove dead copper, pour order 21): 0,59.75
HV on Top Layer "TOP_LAYER_HV_P013" (solid, remove dead copper, pour order 13): 14.45,5.75 14.45,15.5 20,15.5 20,24 7.75,24 7.75,30.829 20.949,30.829 20.949,32 24.494,32 24.494,29.575 28.322,29.575 28.397,29.5 28.397,27 25.5,27 25.4,26.9 25.4,5.75
GND on Bottom Layer "BOTTOM_LAYER_GND_P047" (solid, remove dead copper, pour order 47): 45,60.259 45,0.254 85.25,0.254 85.25,60.259
PGND on Bottom Layer "BOTTOM_LAYER_PGND_P045" (solid, remove dead copper, pour order 45): 0,60.005 0,0 35,0 35,60.005

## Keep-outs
Keep-Out Layer:
  text ".Layer_Name" at 14.656,-21.806 h1.52

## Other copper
Top Layer:
  text ".Layer_Name" at 14.656,-21.806 h1.52
Bottom Layer:
  text ".Layer_Name" at 14.656,-21.806 h1.52

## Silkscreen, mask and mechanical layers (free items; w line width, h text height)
Top Overlay:
  lines w0.1: 12.75,56.013 12.75,57.5 15.037,57.5 15.037,56.013 12.75,56.013
  text "'.PRJ_Number'.PCB_Rev" at 28.085,2.75 h2.75
  text ".Layer_Name" at 14.656,-21.806 h1.52
Bottom Overlay:
  text ".Layer_Name" at 14.656,-21.806 h1.52
Top Paste:
  text ".Layer_Name" at 14.656,-21.806 h1.52
Bottom Paste:
  text ".Layer_Name" at 14.656,-21.806 h1.52
Top Solder:
  text ".Layer_Name" at 14.656,-21.806 h1.52
  text ".Layer_Name" at 14.656,-21.806 h1.52
Bottom Solder:
  text ".Layer_Name" at 14.656,-21.806 h1.52
Drill Guide:
  text ".Layer_Name" at 14.656,-21.806 h1.52
M1 Board Outline:
  the board outline again, w0.254
  text ".Layer_Name" at 14.656,-21.806 h1.52
M2 Board Dimensions:
  rectangle: 0,-6.985 3.175,-3.81
  rectangle: 3.175,-10.16 12.7,-6.985
  lines w0.178: 0,-6.985 25.4,-6.985 ; 3.175,-10.16 3.175,-3.81 ; 6.35,-10.16 6.35,-3.81 ; 12.7,-10.16 12.7,-3.81 ; 19.05,-10.16 19.05,-3.81 ; 0,-10.16 25.4,-10.16 25.4,-3.81 0,-3.81 0,-10.16
  text ".Layer_Name" at 14.656,-21.806 h1.52
M3 3D STEP Top:
  text ".Layer_Name" at 14.656,-21.806 h1.52
M4 3D STEP Bottom:
  text ".Layer_Name" at 14.656,-21.806 h1.52
M5 Assembly Top:
  lines w0.254: -7.417,-23.626 160.223,-23.626 ; -7.417,-18.462 160.274,-18.462 ; -7.417,-13.297 -7.417,-28.791 94.31,-28.791 160.274,-28.791 160.274,-13.297 -7.404,-13.297 -7.404,-28.791 32.614,-28.791 ; 55.194,-28.791 55.194,-13.297 ; 87.376,-18.462 87.376,-13.297 ; 108.712,-18.462 108.712,-13.297 ; 124.511,-28.956 124.511,-23.804
  text "COMPONENTS MARKED 'DNP' SHOULD NOT BE POPULATED." at 29.299,-8.09 h1.52
  text "ASSEMBLY VARIANT:" at 29.286,-11.024 h1.52
  text ".VariantName" at 55.601,-11.024 h1.52
  text "PCB VIEWED FROM TOP SIDE" at -5.804,-16.654 h1.52
  text "BOARD #:" at 57.099,-16.654 h1.52
  text ".PRJ_Number" at 70.955,-16.654 h1.52
  text "REV:" at 92.405,-16.654 h1.52
  text ".PCB_Rev" at 99.809,-16.654 h1.52
  text "SVN REV:" at 113.69,-16.654 h1.52
  text ".VersionControl_RevNumber" at 126.543,-16.654 h1.52
  text "TID #:" at 57.099,-21.819 h1.52
  text ".TID" at 70.955,-21.819 h1.52
  text "PLOT NAME =" at -5.804,-27.034 h1.52
  text ".plot_File_Name" at 14.656,-27.034 h1.52
  text "GENERATED    :" at 57.15,-27.034 h1.52
  text ".Print_Date" at 79.235,-27.034 h1.52
  text ".Print_Time" at 97.752,-27.034 h1.52
  text "TEXAS INSTRUMENTS" at 129.87,-27.034 h1.52
M6 Assembly Bottom:
  lines w0.254: -7.429,-18.474 160.261,-18.474 ; -7.379,-23.639 160.261,-23.639 ; 28.334,-28.969 28.334,-23.817 ; 44.133,-18.474 44.133,-13.31 ; 65.468,-18.474 65.468,-13.31 ; 97.65,-28.804 97.65,-13.31 ; 120.231,-28.804 160.249,-28.804 160.249,-13.31 -7.429,-13.31 -7.429,-28.804 58.534,-28.804 160.261,-28.804 160.261,-13.31
  text "COMPONENTS MARKED 'DNP' SHOULD NOT BE POPULATED." at 154.991,-8.077 h1.52
  text ".VariantName" at 128.473,-11.024 h1.52
  text "ASSEMBLY VARIANT:" at 154.864,-11.024 h1.52
  text ".VersionControl_RevNumber" at 26.302,-16.667 h1.52
  text "SVN REV:" at 39.154,-16.667 h1.52
  text ".PCB_Rev" at 53.035,-16.667 h1.52
  text "REV:" at 60.439,-16.667 h1.52
  text ".PRJ_Number" at 81.89,-16.667 h1.52
  text "BOARD #:" at 95.745,-16.667 h1.52
  text "PCB VIEWED FROM BOTTOM SIDE" at 158.648,-16.667 h1.52
  text ".TID" at 81.89,-21.831 h1.52
  text "TID #:" at 95.745,-21.831 h1.52
  text "TEXAS INSTRUMENTS" at 22.974,-27.047 h1.52
  text ".Print_Time" at 55.093,-27.047 h1.52
  text ".Print_Date" at 73.609,-27.047 h1.52
  text "GENERATED    :" at 95.694,-27.047 h1.52
  text ".plot_File_Name" at 138.189,-27.047 h1.52
  text "PLOT NAME =" at 158.648,-27.047 h1.52
M9 Title Sheet:
  drawing of 57 lines, arcs and shapes, not listed
  text "1" at 18.792,204.127 h1.78
  text "2" at 82.182,204.127 h1.78
  text "3" at 145.411,204.127 h1.78
  text "4" at 209.08,204.127 h1.78
  text "5" at 272.555,204.127 h1.78
  text "6" at 336.182,204.127 h1.78
  text "A" at -10.579,175.095 h1.78
  text "A" at 365.341,175.095 h1.78
  text "B" at -10.579,114.643 h1.78
  text "B" at 365.341,114.643 h1.78
  text "C" at -10.579,54.318 h1.78
  text "C" at 365.341,54.318 h1.78
  text "PROJECT TITLE:" at 288.125,7.048 h1.14
  text ".PRJ_Title" at 289.395,3.662 h1.78
  text "DESIGNED FOR:" at 288.125,-0.597 h1.14
  text ".PRJ_Customer" at 289.395,-4.153 h1.78
  text "D" at -10.579,-5.88 h1.78
  text "D" at 365.341,-5.88 h1.78
  text "FILE NAME:" at 288.125,-8.217 h1.14
  text ".PCB_File_Name_No_Path" at 289.395,-11.265 h1.78
  text "Texas Instruments (TI) and/or its licensors do not warrant the accuracy or completeness of this specification" at 161.9,-15.376 h1.14
  text "ENGINEER:" at 288.125,-15.583 h1.14
  text "LAYOUT BY:" at 326.352,-15.583 h1.14
  text "or any information contained therein. TI and/or its licensors do not warrant that this design will meet" at 160.757,-18.237 h1.14
  text ".PRJ_Engineer" at 289.395,-19.52 h1.78
  text ".PCB_Layout" at 327.635,-19.52 h1.78
  text "the specifications, will be suitable for your application or fit for any particular purpose, or will operate in" at 160.757,-21.099 h1.14
  text ".Layer_Name" at 14.656,-21.806 h1.52
  text "ALTIUM DESIGNER VERSION:" at 326.352,-23.457 h1.14
  text "an implementation. TI and/or its licensors do not warrant that the design is production worthy. You should" at 160.757,-23.961 h1.14
  text "completely validate and test your design implementation to confirm the system functionality for your application." at 161.9,-26.822 h1.14
  text ".print_Scale" at 289.395,-26.843 h1.78
  text ".Application_BuildNumber" at 327.635,-26.843 h1.78
  text "1" at 18.792,-32.093 h1.78
  text "2" at 82.182,-32.093 h1.78
  text "3" at 145.411,-32.093 h1.78
  text "4" at 209.08,-32.093 h1.78
  text "5" at 272.555,-32.093 h1.78
  text "6" at 336.182,-32.093 h1.78
M10 Fab Notes:
  drawing of 189 lines, arcs and shapes, not listed
  text "DESIGN INFORMATION" at 314.503,161.447 h1.52
  text "MIN. TRACK WIDTH:" at 298.131,158.091 h1.52
  text "8" at 325.976,158.091 h1.52
  text "MIL" at 329.907,158.091 h1.52
  text "MIN. CLEARANCE:" at 298.131,154.938 h1.52
  text "0.2" at 324.452,154.938 h1.52
  text "mm" at 329.907,154.938 h1.52
  text "MIN. VIA PAD SIZE:" at 298.131,151.785 h1.52
  text "24" at 325.214,151.785 h1.52
  text "MIL" at 329.907,151.785 h1.52
  text "0.05mm (2MIL)" at 315.784,148.486 h1.52
  text "MINIMUM ANNULAR RING" at 289.769,148.277 h1.52
  text "EXTERNAL" at 333.768,148.277 h1.52
  text "PER" at 294.849,145.48 h1.52
  text "IPC-D-275 CLASS 2 LEVEL C" at 300.437,145.48 h1.52
  text "MIL, HOLES" at 338.238,142.928 h1.52
  text "+/-" at 328.27,142.709 h1.52
  text "+/-" at 349.961,142.709 h1.52
  text "REGISTRATION TOLERANCES:" at 289.769,142.682 h1.52
  text "METAL" at 320.243,142.682 h1.52
  text "5" at 334.879,142.683 h1.52
  text "3" at 356.037,142.683 h1.52
  text "MIL" at 358.99,142.682 h1.52
  text "HOLE SIZE TOLERANCE (UNLESS OTHERWISE SPECIFIED):" at 289.769,140.185 h1.52
  text "+/-" at 349.961,140.112 h1.52
  text "3" at 356.037,140.085 h1.52
  text "MIL" at 358.99,140.085 h1.52
  text "MATERIAL:" at 287.87,136.589 h1.52
  text "FR-4 High Tg" at 312.926,133.324 h1.52
  text "X" at 309.257,133.122 h1.52
  text "FR-408" at 298.563,133.007 h1.52
  text "OTHER" at 336.358,133.007 h1.52
  text "62 MIL (1.6mm) +/-10%" at 306.694,129.374 h1.52
  text "X" at 303.643,129.312 h1.52
  text "THICKNESS:" at 289.769,129.165 h1.52
  text "OTHER" at 339.33,129.165 h1.52
  text "TOLERANCE:" at 289.769,125.652 h1.52
  text "X" at 311.314,125.652 h1.52
  text "ANSI IPC-6012 TYPE 3 CLASS 2" at 315.836,125.652 h1.52
  text "OTHER +/-" at 315.835,121.989 h1.52
  text "BOW & TWIST:" at 289.769,118.302 h1.52
  text "X" at 311.314,118.302 h1.52
  text "ANSI IPC-6012 TYPE 3 CLASS 2" at 315.836,118.302 h1.52
  text "OTHER +/-" at 315.835,114.576 h1.52
  text "DRILLING:" at 287.87,111.258 h1.52
  text "NC_DRILL FILES" at 332.599,108.586 h1.52
  text "REFERENCE:" at 289.769,108.486 h1.52
  text "X" at 306.463,108.484 h1.52
  text "AS SHOWN" at 310.984,108.486 h1.52
  text "X" at 329.348,108.486 h1.52
  text "OTHER" at 340.168,104.873 h1.52
  text "PTH COPPER THICKNESS:" at 289.761,104.783 h1.52
  text "X" at 318.697,104.783 h1.52
  text "20-30 um" at 321.948,104.783 h1.52
  text "BOARD FINISH:" at 287.87,101.034 h1.52
  text "SILKSCREEN:" at 291.812,98.237 h1.52
  text "X" at 316.14,98.237 h1.52
  text "TOP" at 319.112,98.237 h1.52
  text "X" at 329.094,98.237 h1.52
  text "BOTTOM" at 332.091,98.237 h1.52
  text "SILKSCREEN COLOR:" at 291.812,94.295 h1.52
  text "X" at 316.115,94.295 h1.52
  text "WHITE" at 319.112,94.295 h1.52
  text "OTHER" at 332.091,94.295 h1.52
  text "X" at 319.442,90.652 h1.52
  text "GREEN" at 322.439,90.652 h1.52
  text "OTHER" at 338.136,90.652 h1.52
  text "SOLDER RESIST COLOR:" at 291.812,90.477 h1.52
  text "X" at 319.442,86.734 h1.52
  text "MATTE" at 322.439,86.734 h1.52
  text "SEMI-GLOSS" at 338.125,86.717 h1.52
  text "IMMERSION GOLD (ENIG)" at 314.819,82.345 h1.52
  text "X" at 310.25,82.25 h1.52
  text "ENEPIG" at 348.793,82.162 h1.52
  text "SURFACE FINISH:" at 287.87,82.136 h1.52
  text "IMM. TIN/SILVER OR EQUIV" at 296.24,78.649 h1.52
  text "OTHER" at 332.599,78.549 h1.52
  text "ARRAY/PANEL:" at 287.87,74.602 h1.52
  text "CUT AND TRIM PER M1 BOARD OUTLINE" at 314.819,74.393 h1.52
  text "N.C. ROUTE" at 314.819,70.94 h1.52
  text "X" at 332.295,70.94 h1.52
  text "V. SCORE" at 336.816,70.94 h1.52
  text "CERTIFICATION:" at 287.87,67.66 h1.52
  text "MATERIALS AND WORKMANSHIP FOR ALL PCBS" at 306.285,67.66 h1.52
  text "TO MEET OR EXCEED THE REQUIREMENTS OF:" at 306.285,65.271 h1.52
  text "X" at 297.078,62.003 h1.52
  text "ANSI IPC-A-600F CLASS ->" at 300.329,62.003 h1.52
  text "X" at 342.188,62.003 h1.52
  text "2" at 344.982,62.003 h1.52
  text "1" at 336.981,61.965 h1.52
  text "3" at 353.973,61.965 h1.52
  text "X" at 317.702,58.252 h1.52
  text "RoHS" at 320.953,58.252 h1.52
  text "OTHER" at 337.321,58.252 h1.52
  text "PER ORDER" at 347.407,58.252 h1.52
  text "ALL BOARDS MUST MEET OR EXCEED UL94-V0 REQUIREMENTS." at 288.569,54.345 h1.52
  text "PCB MUST BEAR THE UL94V-0 UL REGISTERED MATERIAL ID NUMBER" at 288.569,51.397 h1.52
  text "ADDITIONAL REQUIREMENTS:" at 287.87,47.094 h1.52
  text "MICROSECTION:" at 289.769,44.373 h1.52
  text "YES" at 312.775,44.373 h1.52
  text "REQUIRED" at 334.657,40.707 h1.52
  text "BARE BOARD ELEC. TEST:" at 289.769,40.634 h1.52
  text "NONE" at 322.935,40.634 h1.52
  text "PER ORDER" at 349.693,40.634 h1.52
  text "X" at 320.129,40.5 h1.52
  text "XX MIL VIAS REQUIRE NON-CONDUCTIVE FILL AND PLANARIZE" at 294.04,35.428 h1.5
  text "XX MIL VIAS REQUIRE CONDUCTIVE FILL AND PLANARIZE" at 294.243,32.787 h1.52
  text "OUTER XX MIL TRACES REQUIRE 50 OHM SINGLE-ENDED IMPEDANCE" at 294.218,28.637 h1.47
  text "LAYER 2 & 3 (INNER LAYERS) XX MIL WIDE, XX MIL SPACE / TRACES REQUIRE 100 OHM DIFFERENTIAL IMPEDANCE" at 294.015,22.65 h1.52
  text ".Layer_Name" at 14.656,-21.806 h1.52
M11 Gerber Information:
  lines w0.254: -7.417,-23.626 160.223,-23.626 ; -7.417,-18.462 160.274,-18.462 ; -7.417,-13.297 -7.417,-28.791 94.31,-28.791 160.274,-28.791 160.274,-13.297 -7.404,-13.297 -7.404,-28.791 32.614,-28.791 ; 55.194,-28.791 55.194,-13.297 ; 87.376,-18.462 87.376,-13.297 ; 108.712,-18.462 108.712,-13.297 ; 124.511,-28.956 124.511,-23.804
  text "ALL ARTWORK VIEWED FROM TOP SIDE" at -5.804,-16.654 h1.52
  text "BOARD #:" at 57.099,-16.654 h1.52
  text ".PRJ_Number" at 70.955,-16.654 h1.52
  text "REV:" at 92.405,-16.654 h1.52
  text ".PCB_Rev" at 99.809,-16.654 h1.52
  text "SVN REV:" at 113.69,-16.654 h1.52
  text ".VersionControl_RevNumber" at 126.543,-16.654 h1.52
  text "LAYER NAME =" at -5.804,-21.806 h1.52
  text "TID #:" at 57.099,-21.819 h1.52
  text ".TID" at 70.955,-21.819 h1.52
  text "PLOT NAME =" at -5.804,-27.034 h1.52
  text ".plot_File_Name" at 14.656,-27.034 h1.52
  text "GENERATED    :" at 57.15,-27.034 h1.52
  text ".Print_Date" at 79.235,-27.034 h1.52
  text ".Print_Time" at 97.752,-27.034 h1.52
  text "TEXAS INSTRUMENTS" at 129.87,-27.034 h1.52
M12 Stackup:
  drawing of 191 lines, arcs and shapes, not listed
  text "Layer" at 247.997,190.656 h1.52
  text "Name" at 258.408,190.656 h1.52
  text "Material" at 282.024,190.656 h1.52
  text "Thickness" at 303.862,190.656 h1.52
  text "Constant" at 320.368,190.656 h1.52
  text "Board Layer Stack" at 334.842,190.656 h1.52
  text "1" at 247.997,187.608 h1.52
  text "Top Overlay" at 258.408,187.608 h1.52
  text "2" at 247.997,184.56 h1.52
  text "Top Solder" at 258.408,184.56 h1.52
  text "Solder Resist" at 282.024,184.56 h1.52
  text "0.40mil" at 303.862,184.56 h1.52
  text "3.5" at 320.368,184.56 h1.52
  text "3" at 247.997,181.512 h1.52
  text "Top Layer" at 258.408,181.512 h1.52
  text "Copper" at 282.024,181.512 h1.52
  text "1.40mil" at 303.862,181.512 h1.52
  text "4" at 247.997,178.464 h1.52
  text "Dielectric1" at 258.408,178.464 h1.52
  text "FR-4" at 282.024,178.464 h1.52
  text "59.20mil" at 303.862,178.464 h1.52
  text "4.8" at 320.368,178.464 h1.52
  text "5" at 247.997,175.416 h1.52
  text "Bottom Layer" at 258.408,175.416 h1.52
  text "Copper" at 282.024,175.416 h1.52
  text "1.40mil" at 303.862,175.416 h1.52
  text "6" at 247.997,172.368 h1.52
  text "Bottom Solder" at 258.408,172.368 h1.52
  text "Solder Resist" at 282.024,172.368 h1.52
  text "0.40mil" at 303.862,172.368 h1.52
  text "3.5" at 320.368,172.368 h1.52
  text "7" at 247.997,169.32 h1.52
  text "Bottom Overlay" at 258.408,169.32 h1.52
  text ".Layer_Name" at 14.656,-21.806 h1.52
M13 Component Bodies Top:
  text ".Layer_Name" at 14.656,-21.806 h1.52
M14 Component Bodies Bottom:
  text ".Layer_Name" at 14.656,-21.806 h1.52
M15 Courtyards Top:
  text ".Layer_Name" at 14.656,-21.806 h1.52
M16 Courtyards Bottom:
  text ".Layer_Name" at 14.656,-21.806 h1.52
Drill Drawing:
  circle w0.254: c189.376,153.671 r0.702
  lines w0.254: 188.675,143.846 189.026,143.846 189.026,143.496 189.727,143.496 189.727,143.846 190.078,143.846 190.078,144.548 189.727,144.548 189.727,144.899 189.026,144.899 189.026,144.548 188.675,144.548 188.675,143.846 ; 188.675,148.057 190.078,148.057 189.376,146.653 188.675,148.057 ; 188.675,149.811 190.078,149.811 190.078,151.215 188.675,151.215 188.675,149.811 ; 188.675,156.127 189.376,156.477 190.078,156.127 189.727,156.828 190.078,157.53 189.376,157.179 188.675,157.53 189.026,156.828 188.675,156.127 ; 188.675,159.284 188.675,159.635 189.026,159.986 188.675,160.337 188.675,160.688 189.026,160.688 189.376,160.337 189.727,160.688 190.078,160.688 190.078,160.337 189.727,159.986 190.078,159.635 190.078,159.284 189.727,159.284 189.376,159.635 189.026,159.284 188.675,159.284
  lines w0.305: 187.402,142.548 269.482,142.548 ; 187.402,161.495 269.482,161.495 ; 195.984,139.391 195.984,164.652 ; 204.417,139.391 204.417,164.652 ; 220.586,139.391 220.586,164.652 ; 227.168,139.391 227.168,164.652 ; 236.697,139.391 236.697,164.652 ; 255.095,139.391 255.095,164.652 ; 187.402,139.391 269.482,139.391 269.482,164.652 187.402,164.652 187.402,139.391
  text "Symbol" at 189.297,162.442 h1.83
  text "Quantity" at 196.931,162.442 h1.83
  text "Finished Hole Size" at 205.364,162.442 h1.83
  text "Plated" at 221.533,162.442 h1.83
  text "Hole Type" at 228.115,162.442 h1.83
  text "Drill Layer Pair" at 237.644,162.442 h1.83
  text "Hole Tolerance" at 256.042,162.442 h1.83
  text "4" at 196.931,159.284 h1.52
  text "0.305mm (12.00mil)" at 205.364,159.284 h1.52
  text "PTH" at 221.533,159.284 h1.52
  text "Round" at 228.115,159.284 h1.52
  text "Top Layer - Bottom Layer" at 237.644,159.284 h1.52
  text "25" at 196.931,156.127 h1.52
  text "0.711mm (28.00mil)" at 205.364,156.127 h1.52
  text "PTH" at 221.533,156.127 h1.52
  text "Round" at 228.115,156.127 h1.52
  text "Top Layer - Bottom Layer" at 237.644,156.127 h1.52
  text "4" at 196.931,152.969 h1.52
  text "0.900mm (35.43mil)" at 205.364,152.969 h1.52
  text "PTH" at 221.533,152.969 h1.52
  text "Round" at 228.115,152.969 h1.52
  text "Top Layer - Bottom Layer" at 237.644,152.969 h1.52
  text "3" at 196.931,149.811 h1.52
  text "1.016mm (40.00mil)" at 205.364,149.811 h1.52
  text "PTH" at 221.533,149.811 h1.52
  text "Round" at 228.115,149.811 h1.52
  text "Top Layer - Bottom Layer" at 237.644,149.811 h1.52
  text "4" at 196.931,146.653 h1.52
  text "1.250mm (49.21mil)" at 205.364,146.653 h1.52
  text "PTH" at 221.533,146.653 h1.52
  text "Round" at 228.115,146.653 h1.52
  text "Top Layer - Bottom Layer" at 237.644,146.653 h1.52
  text "1" at 196.931,143.496 h1.52
  text "1.600mm (63.00mil)" at 205.364,143.496 h1.52
  text "PTH" at 221.533,143.496 h1.52
  text "Round" at 228.115,143.496 h1.52
  text "Top Layer - Bottom Layer" at 237.644,143.496 h1.52
  text "41 Total" at 196.931,140.338 h1.52
  text ".Layer_Name" at 14.656,-21.806 h1.52
M17 Embedded Cavity:
  text ".Layer_Name" at 14.656,-21.806 h1.52
M18 Embedded Assembly:
  text ".Layer_Name" at 14.656,-21.806 h1.52
M19 Embedded Keepout:
  text ".Layer_Name" at 14.656,-21.806 h1.52

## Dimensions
0,-10.16 to 25.4,-10.16 on M2 Board Dimensions
0,0 to 0,60.005 on M2 Board Dimensions
0,0 to 85.25,0 on M2 Board Dimensions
